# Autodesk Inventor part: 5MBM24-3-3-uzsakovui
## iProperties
Created: 2010-09
Part Number: 5MBM24-3-3-uzsakovui
Document SubType Name: Modeling
Designer: Darius
Author: Darius
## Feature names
1. Base1
